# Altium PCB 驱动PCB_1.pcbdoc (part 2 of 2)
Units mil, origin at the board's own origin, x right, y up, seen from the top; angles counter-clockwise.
Board outline 1900 x 3705 mil, 2 copper layers (Top Layer, Bottom Layer); 43 components, 46 nets, 190 pads, 128 vias.
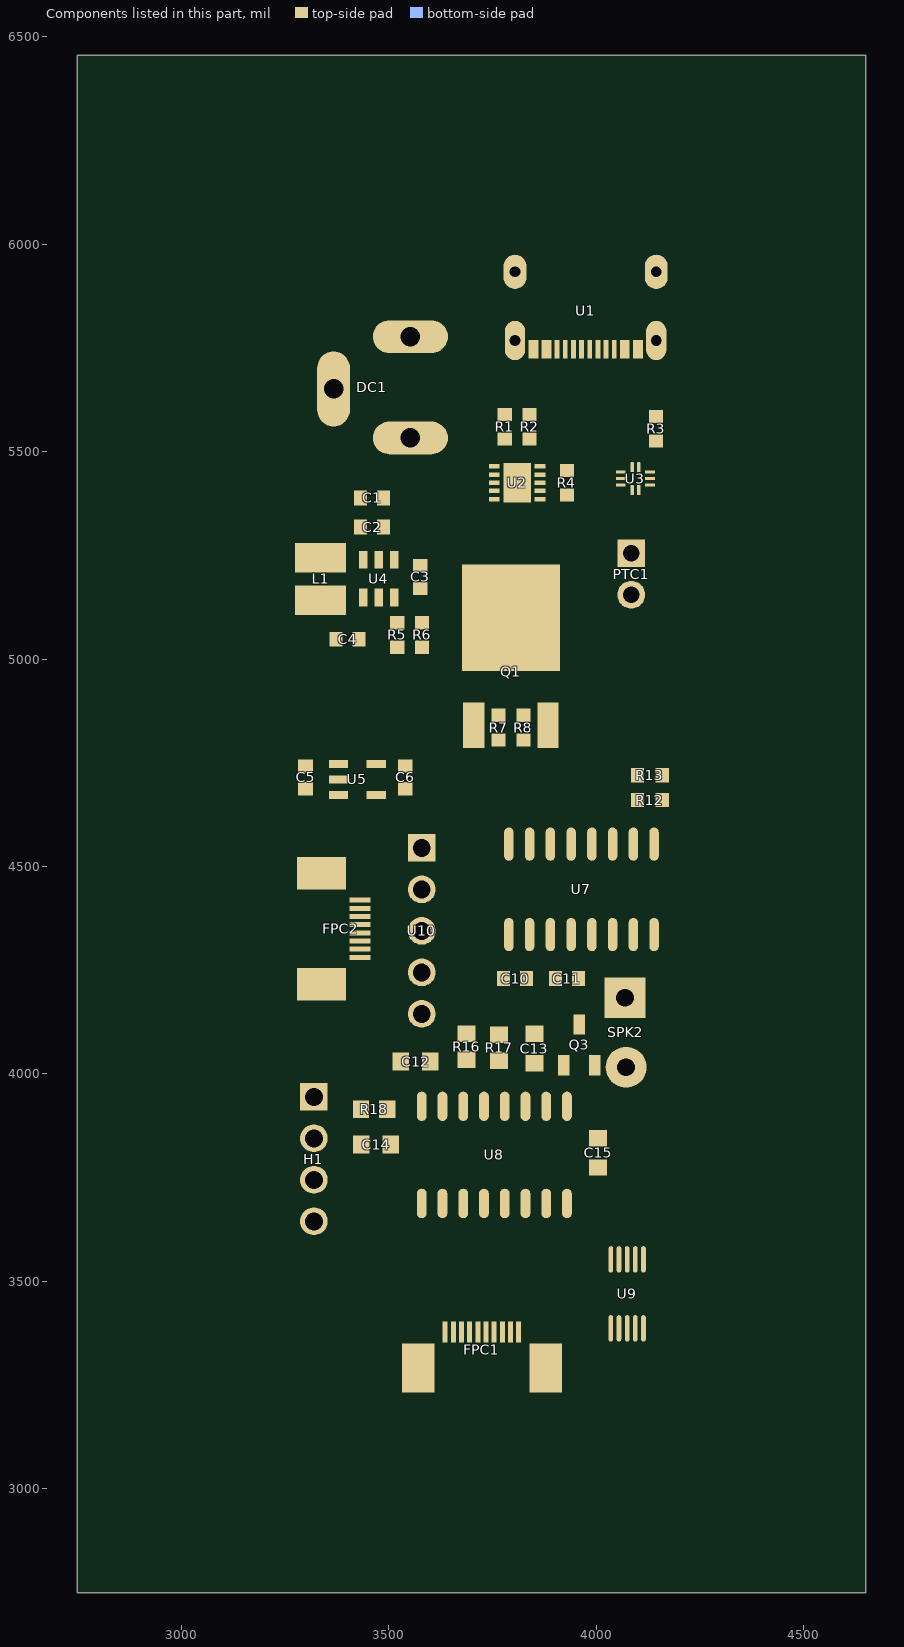
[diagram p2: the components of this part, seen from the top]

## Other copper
Top Layer:
  region net $2N1457: 3276.08,5208.01 3276.08,5283.01 3451.08,5283.01 3451.08,5208.01
  region net $2N1461: 3501.08,5167.61 3526.08,5168.01 3526.08,5113.01 3602.09,5113.01 3602.09,5069.79 3501.08,5069.79
  region net GND: 3486.08,5168.01 3461.84,5168.01 3461.84,5098.01 3406.08,5098.01 3406.08,4900.78 3486.08,4900.78
  region net VIN: 3461.17,5215.98 3461.17,5407.73 3460.78,5407.73 3460.78,5635 3565,5635 3665,5735 3665,5875 4060.98,5875 4060.98,5772.84 4013.78,5830 3945,5830 3890,5775 3886.42,5778.58 3886.42,5826.6 3786.6,5826.6 3765,5805 3765,5670 3667.98,5572.98 3667.98,5502.98 3572.73,5407.73 3544.82,5407.73 3544.82,5257.44 3526.04,5257.44 3525.67,5216.22 3502.75,5216.22 3502.99,5259.9 3488.36,5260 3488.36,5215.98
  region net 5V: 3275.85,4788.09 3276.08,4788.09 3276.08,5178.01 3391.08,5178.01 3391.08,4863.01 3499.71,4863.01 3499.71,5058.01 3553.49,5058.01 3553.49,4778.01 3436.91,4778.01 3436.91,4661.48 3355,4661.48 3355,4685 3409.89,4685 3409.89,4736.42 3330.25,4736.42 3330.25,4730.85 3275.85,4730.85
  region net GND: 3399.05,4720.38 3276.57,4720.31 3276.57,4629.64 3345.75,4629.64 3345,4700 3399.05,4700
  region net 3V3: 3445,4761.2 3445,4695 3500.97,4695 3500.97,4725.97 3560.45,4725.97 3560.45,4761.2
  region net 3V3: 3775,3335 3775,3285 3785,3275 3799.68,3275 3809.68,3285 3809.68,3335 3799.68,3345 3785,3345
  region net $2N1457: 3543.63,5203.34 3552.31,5226.16 ccw(c3536.35,5241.32) 3558.36,5241.32 3558.36,5209.82 ccw(c3559.34,5187.64)
  region net GND: 3437.91,5355.51 3427.91,5355.51 ccw(c3409.16,5355.51) 3420.41,5370.51 3445.41,5370.51 ccw(c3456.66,5355.51)
  region net GND: 3427.91,5350.94 3437.91,5350.94 ccw(c3456.66,5350.94) 3445.41,5335.94 3420.41,5335.94 ccw(c3409.16,5350.94)
  region net 3V3: 3553.98,4763.61 3562.18,4757.67 ccw(c3585.39,4742.6) 3557.72,4742.6 3538.07,4758.31 ccw(c3538.07,4784.82)
  region net $2N1719: 3835,4262.72 3845,4262.72 ccw(c3880.66,4262.72) 3848.31,4247.72 3827.5,4247.72 ccw(c3816.25,4262.72)
  region net $2N1719: 3863.31,4235 3863.31,4225 ccw(c3863.31,4206.25) 3848.31,4217.5 3848.31,4242.5 ccw(c3863.31,4253.75)
  region net $2N1719: 3871.69,4225 3871.69,4235 ccw(c3871.69,4253.75) 3886.69,4242.5 3886.69,4217.5 ccw(c3871.69,4206.25)
  region net $2N3517: 3500.43,3866.65 3510.43,3866.65 ccw(c3529.18,3866.65) 3517.93,3851.65 3492.93,3851.65 ccw(c3481.68,3866.65)
  region net A-: 3450.43,3787.07 3435.43,3787.07 ccw(c3409.69,3787.07) 3424.18,3808.35 3454.24,3808.35 ccw(c3511.64,3787.07)
  region net A-: 3392.38,3837.5 3392.38,3852.5 ccw(c3414.87,4151.1) 3414.88,3851.65 3414.88,3826.25 ccw(c3392.38,3809.38)
  region net E+: 3835.3,3999.27 3824.7,4009.87 ccw(c3782.88,4030.67) 3829.58,4030.67 3858.07,4006.12 ccw(c3858.07,3964.89)
  region net E+: 3824.28,4045.69 3833.32,4050.79 ccw(c3849.23,4072.01) 3849.23,4045.49 3829.58,4029.78 ccw(c3803.07,4029.78)
  region net E+: 3868.27,4053.45 3880.84,4044.81 ccw(c3912.66,4020.94) 3872.89,4020.94 3844.4,4045.49 ccw(c3844.4,4085.27)
  region net 3V3: 3975.39,3866 3989.54,3873.07 ccw(c4013.4,3904.89) 4013.4,3865.11 3983.35,3842.14 ccw(c3943.57,3842.14)
  region net 3V3: 3970.43,3837.93 3970.43,3852.93 ccw(c3970.43,3865.97) 3983.35,3864.18 3983.35,3826.68 ccw(c3970.43,3824.89)
  region net VIN: 3592.51,5422.48 3512.51,5422.48 3512.78,5429.14 3513.49,5435.75 3514.53,5442.25 3515.77,5448.59 3518.35,5460.61 3519.45,5466.17 3520.26,5471.37 3520.65,5476.15 3520.65,5478.37 3520.5,5480.47 3520.18,5482.43 3519.68,5484.26 3518.99,5485.94 3518.08,5487.48 3516.95,5488.86 3515.57,5490.07 3513.93,5491.12 3512.02,5491.99 3509.82,5492.68 3507.32,5493.18 3504.49,5493.49 3501.33,5493.59 3603.7,5493.59 3600.54,5493.49 3597.71,5493.18 3595.21,5492.68 3593.01,5491.99 3591.1,5491.12 3589.46,5490.07 3588.08,5488.86 3586.95,5487.48 3586.04,5485.94 3585.35,5484.26 3584.85,5482.43 3584.53,5480.47 3584.38,5478.37 3584.38,5476.15 3584.77,5471.37 3585.58,5466.17 3586.68,5460.61 3589.26,5448.59 3590.5,5442.25 3591.54,5435.75 3592.25,5429.14
  region net ADC_VIN: 3631.41,3418.59 3641.41,3418.59 ccw(c3763.07,3418.59) 3642.32,3403.77 3630.51,3403.77 ccw(c3509.76,3418.59)
  region net GND: 3661.11,3337.59 3651.11,3337.59 ccw(c3526.41,3337.59) 3650.2,3352.59 3662.01,3352.59 ccw(c3785.8,3337.59)
  region net 3V3: 3798.89,3337.59 3788.89,3337.59 ccw(c3664.2,3337.59) 3787.99,3352.59 3799.8,3352.59 ccw(c3923.59,3337.59)
  region net SW: 3834.49,3385 3834.49,3375 ccw(c3834.49,3356.25) 3819.49,3367.5 3819.49,3392.5 ccw(c3834.49,3403.75)
  region net VIN: 4129.07,5225.07 4114.93,5210.93 ccw(c4083.11,5168.5) 4083.11,5221.54 4118.46,5256.89 ccw(c4171.5,5256.89)
  region net $2N173: 4033.11,5195 4033.11,5115 ccw(c4033.11,4965) 3913.11,5055 3913.11,5227.56 ccw(c4033.11,5432.42)
  region net $2N169: 3746.11,4869.66 3746.11,4859.66 ccw(c3746.11,4840.91) 3731.11,4852.16 3731.11,4877.16 ccw(c3746.11,4888.41)
  region net E+: 3944.63,4111.7 3944.63,4126.7 ccw(c3905.64,4137.95) 3946.22,4137.95 3946.22,4100.45 ccw(c3905.64,4100.45)
  region net 3V3: 4004.9,3989.4 3989.9,3989.4 ccw(c3983.09,3989.4) 3983.62,3996.19 4011.18,3996.19 ccw(c4011.71,3989.4)
  region net $2N3503: 3896.34,3987.46 3900.93,4006.2 ccw(c3878.85,4028.28) 3908.82,4019.52 3908.82,3996.19 ccw(c3927.23,3956.57)
  region net $2N169: 3732.99,4859.66 3732.99,4869.66 ccw(c3732.99,4888.41) 3747.99,4877.16 3747.99,4852.16 ccw(c3732.99,4840.91)
  region net $2N169: 3797.01,4869.66 3797.01,4859.66 ccw(c3797.01,4840.91) 3782.01,4852.16 3782.01,4877.16 ccw(c3797.01,4888.41)
  region net PTC: 3787.31,4784.76 3773.77,4784.16 ccw(c3757.86,4762.95) 3757.86,4789.46 3782.01,4800.67 ccw(c3808.52,4800.67)
  region net $2N860: 3747.99,5525.34 3747.99,5535.34 ccw(c3747.99,5554.09) 3762.99,5542.84 3762.99,5517.84 ccw(c3747.99,5506.59)
  region net VIN: 3940,5375 3920,5375 ccw(c3912.99,5371.73) 3912.99,5379.46 3947.01,5379.46 ccw(c3947.01,5371.73)
  region net ADC_VIN: 4159.69,4637.62 4136.75,4628.82 ccw(c4119.2,4646.37) 4143.78,4642.99 4175.54,4642.99 ccw(c4175.54,4616.94)
  region net ADC_VIN: 4138.48,4674.79 4145.1,4682.31 ccw(c4161.01,4703.52) 4161.01,4677.01 4143.78,4658.88 ccw(c4117.27,4658.88)
  region net ADC_VIN: 4121.52,4705.89 4115.58,4697.69 ccw(c4099.67,4676.48) 4099.67,4702.99 4116.22,4721.8 ccw(c4142.73,4721.8)
  region net VIN: 4154.66,4752.01 4164.66,4752.01 ccw(c4183.41,4752.01) 4172.16,4737.01 4147.16,4737.01 ccw(c4135.91,4752.01)
  region net $2N169: 3792.99,4859.66 3792.99,4869.66 ccw(c3792.99,4888.41) 3807.99,4877.16 3807.99,4852.16 ccw(c3792.99,4840.91)
  region net $2N861: 3825.89,5509.16 3817.69,5515.1 ccw(c3796.48,5531.01) 3822.99,5531.01 3841.8,5514.46 ccw(c3841.8,5487.95)
  region net SW: 4150,5494.46 4140,5494.46 ccw(c4121.25,5494.46) 4132.5,5509.46 4157.5,5509.46 ccw(c4168.75,5494.46)
  region net E+: 3795.78,4088.33 3801.21,4068.76 ccw(c3779.13,4046.68) 3787.89,4076.65 3787.89,4101.65 ccw(c3817.86,4110.41)
  region net $2N3512: 3729.58,4026.75 3729.58,4036.75 ccw(c3729.58,4055.5) 3744.58,4044.25 3744.58,4019.25 ccw(c3729.58,4008)
  region net $2N3512: 3785,3997.06 3775,3997.06 ccw(c3756.25,3997.06) 3767.5,4012.06 3787.89,4012.06 ccw(c3825.38,3997.06)
  region net $2N3512: 3724.54,4036.75 3724.54,4026.75 ccw(c3724.54,4008) 3709.54,4019.25 3709.54,4044.25 ccw(c3724.54,4055.5)
  region net $2N3517: 3510.43,3878.35 3500.43,3878.35 ccw(c3481.68,3878.35) 3492.93,3893.35 3516.18,3893.35 ccw(c3532.86,3878.35)
  region net $2N3517: 3538.68,3922.5 3538.68,3907.5 ccw(c3538.68,3879.38) 3516.18,3896.25 3516.18,3933.75 ccw(c3538.68,3950.62)
  region net A+: 3405.87,3932.03 3414.51,3944.61 ccw(c3438.37,3976.43) 3438.37,3936.65 3413.82,3908.17 ccw(c3374.05,3908.17)
  region net SCK: 3685,3649.38 3675,3649.38 3674.71,3652.13 3673.94,3654.75 3672.84,3657.16 3671.59,3659.32 3669.25,3662.67 3668.48,3663.75 3668.19,3664.38 3691.81,3664.38 3691.52,3663.75 3690.75,3662.67 3688.41,3659.32 3687.16,3657.16 3686.06,3654.75 3685.29,3652.13
  region net DOUT: 3735,3649.38 3725,3649.38 3724.71,3652.13 3723.94,3654.75 3722.84,3657.16 3721.59,3659.32 3719.25,3662.67 3718.48,3663.75 3718.19,3664.38 3741.81,3664.38 3741.52,3663.75 3740.75,3662.67 3738.41,3659.32 3737.16,3657.16 3736.06,3654.75 3735.29,3652.13
  region net 3V3: 3922.5,3734.12 3937.5,3734.12 3937.69,3729.97 3938.17,3726 3938.86,3722.32 3939.66,3719.03 3941.14,3713.98 3941.81,3711.62 3918.19,3711.62 3918.86,3713.98 3920.34,3719.03 3921.14,3722.32 3921.83,3726 3922.31,3729.97
  region net 3V3: 3953.65,3674.96 3958.32,3649.07 3955.33,3652.48 3952.38,3656.4 3947.08,3663.93 3944.94,3666.58 3944.04,3667.42 3943.27,3667.86 3942.65,3667.83 3942.19,3667.28 3941.91,3666.15 3941.81,3664.38 3941.81,3694.94 3942.08,3691.92 3942.83,3689.12 3944,3686.5 3945.51,3684.03 3947.3,3681.67 3949.3,3679.4
  region net $2N3517: 3545.69,3907.5 3545.69,3922.5 3549.89,3922.52 3553.95,3922.68 3557.75,3923.09 3561.16,3923.91 3562.67,3924.5 3564.04,3925.25 3565.24,3926.16 3566.26,3927.25 3567.08,3928.53 3567.68,3930.04 3568.06,3931.77 3568.19,3933.75 3568.19,3898.38 3568.06,3900.33 3567.68,3902 3567.08,3903.4 3566.26,3904.55 3565.24,3905.48 3564.04,3906.21 3562.67,3906.76 3561.16,3907.16 3557.75,3907.58 3553.95,3907.66
  region net A-: 3637.5,3875.88 3622.5,3875.88 3622.31,3880.03 3621.83,3884 3621.14,3887.68 3620.34,3890.97 3618.86,3896.02 3618.19,3898.38 3641.81,3898.38 3641.14,3896.02 3639.66,3890.97 3638.86,3887.68 3638.17,3884 3637.69,3880.03
  region net $2N3514: 3675,3960.62 3685,3960.62 3685.29,3957.87 3686.06,3955.25 3687.16,3952.84 3688.41,3950.68 3690.75,3947.33 3691.52,3946.25 3691.81,3945.62 3668.19,3945.62 3668.48,3946.25 3669.25,3947.33 3671.59,3950.68 3672.84,3952.84 3673.94,3955.25 3674.71,3957.87
  region net $2N3512: 3775,3960.62 3785,3960.62 3785.29,3957.87 3786.06,3955.25 3787.16,3952.84 3788.41,3950.68 3790.75,3947.33 3791.52,3946.25 3791.81,3945.62 3768.19,3945.62 3768.48,3946.25 3769.25,3947.33 3771.59,3950.68 3772.84,3952.84 3773.94,3955.25 3774.71,3957.87
  region net E+: 3822.5,3968.12 3837.5,3968.12 3837.69,3963.97 3838.17,3960 3838.86,3956.32 3839.66,3953.03 3841.14,3947.98 3841.81,3945.62 3818.19,3945.62 3818.86,3947.98 3820.34,3953.03 3821.14,3956.32 3821.83,3960 3822.31,3963.97
  region net E+: 3840,3868.38 3820,3868.38 3819.72,3879.25 3819.09,3888.63 3818.19,3898.38 3841.81,3898.38 3840.91,3888.63 3840.28,3879.25
  region net $2N3503: 3875,3960.62 3885,3960.62 3885.29,3957.87 3886.06,3955.25 3887.16,3952.84 3888.41,3950.68 3890.75,3947.33 3891.52,3946.25 3891.81,3945.62 3868.19,3945.62 3868.48,3946.25 3869.25,3947.33 3871.59,3950.68 3872.84,3952.84 3873.94,3955.25 3874.71,3957.87
  region net 3V3: 3953.65,3908.96 3958.32,3883.07 3955.33,3886.48 3952.38,3890.4 3947.08,3897.93 3944.94,3900.58 3944.04,3901.42 3943.27,3901.86 3942.65,3901.83 3942.19,3901.28 3941.91,3900.15 3941.81,3898.38 3941.81,3928.94 3942.08,3925.92 3942.83,3923.12 3944,3920.5 3945.51,3918.03 3947.3,3915.67 3949.3,3913.4
  region net 3V3: 3958.32,3960.93 3953.65,3935.04 3949.3,3930.6 3947.3,3928.33 3945.51,3925.97 3944,3923.5 3942.83,3920.88 3942.08,3918.08 3941.81,3915.06 3941.81,3945.62 3941.91,3943.85 3942.19,3942.72 3942.65,3942.17 3943.27,3942.14 3944.04,3942.58 3944.94,3943.42 3947.08,3946.07 3952.38,3953.6 3955.33,3957.52
  region net $2N1457: 3449.36,5209.02 3439.36,5209.02 ccw(c3430.5,5209.02) 3431.86,5217.77 3449.22,5217.77 ccw(c3721.11,5217.77)
  region net $2N1458: 3433.74,5172.82 3443.74,5172.82 ccw(c3449.22,5175.66) 3449.22,5169.49 3428.27,5169.49 ccw(c3428.27,5175.66)
  region net CC1: 4029.21,5719.56 4019.21,5719.56 ccw(c4006.64,5719.56) 4018.3,5724.24 4030.12,5724.24 ccw(c4041.78,5719.56)
  region net CC2: 3911.1,5709.24 3901.1,5709.24 ccw(c3776.41,5709.24) 3900.19,5724.24 3912.01,5724.24 ccw(c4035.79,5709.24)
  region net VIN: 4077.5,5710 4062.5,5710 ccw(c4051.47,5724.24) 4069.48,5724.24 4081.3,5724.24 ccw(c4106.12,5710)
  region net CC1: 3890,5449.69 3890,5439.69 ccw(c3890,5310.3) 3878.5,5439.18 3878.5,5450.2 ccw(c3890,5579.08)
  region net CC2: 3860.41,5480.41 3870.41,5480.41 ccw(c3881.55,5480.41) 3877.91,5469.88 3852.91,5469.88 ccw(c3849.27,5480.41)
  region net USBDM: 3985,4597.84 3995,4597.84 3995.27,4595.08 3995.98,4592.47 3996.99,4590.06 3998.15,4587.9 4000.31,4584.55 4001.03,4583.46 4001.3,4582.84 3978.7,4582.84 3978.97,4583.46 3979.69,4584.55 3981.85,4587.9 3983.01,4590.06 3984.02,4592.47 3984.73,4595.08
  region net USBDP: 3935,4597.84 3945,4597.84 3945.27,4595.08 3945.98,4592.47 3946.99,4590.06 3948.15,4587.9 3950.31,4584.55 3951.03,4583.46 3951.3,4582.84 3928.7,4582.84 3928.97,4583.46 3929.69,4584.55 3931.85,4587.9 3933.01,4590.06 3934.02,4592.47 3934.73,4595.08
  region net CH7800_RX: 4159.19,4323.86 4164.62,4304.29 4160.23,4308.92 4158,4311.23 4155.91,4313.19 4154.07,4314.53 4153.29,4314.88 4152.61,4314.98 4152.06,4314.8 4151.65,4314.29 4151.39,4313.43 4151.3,4312.18 4151.3,4337.18 4151.48,4335.17 4151.98,4333.3 4152.76,4331.55 4153.77,4329.91 4154.96,4328.34 4156.29,4326.82
  region net CH7800_TX: 4104.14,4297.93 4094.91,4293.02 4092.91,4294.67 4091.06,4295.62 4089.32,4296.12 4087.66,4296.41 4086.03,4296.73 4084.4,4297.33 4082.74,4298.44 4081,4300.33 4099,4314 4099.83,4312.77 4100.44,4311.62 4101.11,4309.49 4101.29,4307.53 4101.25,4305.68 4101.24,4303.86 4101.54,4302.01 4101.89,4301.05 4102.42,4300.06 4103.16,4299.02
  region net SPK1: 4047.5,4284.66 4032.5,4284.66 4032.34,4288.82 4031.91,4292.78 4031.3,4296.46 4030.6,4299.75 4029.29,4304.81 4028.7,4307.16 4051.3,4307.16 4050.71,4304.81 4049.4,4299.75 4048.7,4296.46 4048.09,4292.78 4047.66,4288.82
  region net SPK2: 3997.5,4284.66 3982.5,4284.66 3982.34,4288.82 3981.91,4292.78 3981.3,4296.46 3980.6,4299.75 3979.29,4304.81 3978.7,4307.16 4001.3,4307.16 4000.71,4304.81 3999.4,4299.75 3998.7,4296.46 3998.09,4292.78 3997.66,4288.82
  region net 5V: 3868.24,4386.16 3890.14,4385.46 3892.22,4383.3 3894.24,4380.99 3896.12,4378.55 3897.81,4376 3899.24,4373.33 3900.34,4370.57 3901.05,4367.72 3901.3,4364.8 3878.7,4364.8 3878.47,4367.63 3877.8,4370.52 3876.77,4373.43 3875.43,4376.29 3873.85,4379.05 3872.08,4381.65 3870.19,4384.04
  region net $2N1719: 3845,4292.16 3835,4292.16 3834.73,4294.92 3834.02,4297.53 3833.01,4299.94 3831.85,4302.1 3829.69,4305.45 3828.97,4306.54 3828.7,4307.16 3851.3,4307.16 3851.03,4306.54 3850.31,4305.45 3848.15,4302.1 3846.99,4299.94 3845.98,4297.53 3845.27,4294.92
  region net SW: 4135.18,5462.57 4148.54,5461.78 ccw(c7232.44,2377.87) 4141.45,5454.68 4121.86,5454.68 ccw(c4113.1,5484.65)
  region net GND: 4037.95,5465.3 4054.82,5462.57 ccw(c4076.9,5484.65) 4068.14,5454.68 4048.55,5454.68 ccw(c-2852.18,-1424.92)
  region net 3V3: 4022.23,3395.7 4021.44,3410.63 4024.18,3408.09 4025.63,3406.94 4027.01,3406.04 4028.24,3405.51 4029.22,3405.47 4029.6,3405.68 4029.88,3406.06 4030.06,3406.62 4030.12,3407.38 4030.12,3382.38 4029.94,3384.39 4029.44,3386.26 4028.66,3388.01 4027.65,3389.66 4026.46,3391.23 4025.12,3392.74
  region net SW: 4099.69,3349.69 4089.69,3349.69 4089.43,3356.78 4089.18,3360.55 4100.2,3360.55 4099.95,3356.78
  region net CH7800_RX: 4131.93,3391.93 4131.93,3381.93 4129.68,3381.85 4127.51,3381.61 4125.47,3381.15 4123.65,3380.44 4122.11,3379.45 4120.92,3378.14 4120.15,3376.48 4119.88,3374.43 4119.88,3399.43 4120.15,3397.38 4120.92,3395.72 4122.11,3394.41 4123.65,3393.42 4125.47,3392.71 4127.51,3392.25 4129.68,3392.01
  region net DOUT: 4015.12,3548.07 4015.12,3558.07 4020.63,3558.19 4023.16,3558.47 4025.43,3559.01 4027.35,3559.9 4028.15,3560.51 4028.83,3561.23 4029.38,3562.09 4029.78,3563.09 4030.03,3564.25 4030.12,3565.57 4030.12,3540.57 4030.03,3541.89 4029.78,3543.05 4029.38,3544.05 4028.83,3544.91 4028.15,3545.63 4027.35,3546.24 4025.43,3547.13 4023.16,3547.67 4020.63,3547.95
  region net ESP_RX: 4060.32,3511.69 4050.32,3511.69 4050.06,3521.63 4049.81,3526.69 4060.83,3526.69 4060.58,3521.63
  region net SPK2: 4030.87,4092.24 4075.02,4069.31 4077.31,4067.16 4079.47,4065.43 4081.5,4064.06 4083.43,4062.98 4085.28,4062.15 4087.07,4061.49 4090.56,4060.49 4094.07,4059.51 4095.88,4058.87 4097.76,4058.07 4099.72,4057.03 4101.8,4055.7 4104,4054.02 4106.36,4051.93 4033.25,4045.9 4034.9,4048.36 4036.32,4051.03 4037.49,4053.88 4038.43,4056.86 4039.12,4059.96 4039.58,4063.14 4039.79,4066.37 4039.77,4069.61 4039.5,4072.83 4038.99,4076.01 4038.24,4079.1 4037.25,4082.08 4036.02,4084.92 4034.55,4087.58 4032.83,4090.03
  region net SPK2: 4030.9,4092.21 4075.78,4068.55 4078.08,4066.4 4080.24,4064.68 4082.29,4063.32 4084.24,4062.26 4086.1,4061.44 4087.91,4060.81 4091.44,4059.84 4094.96,4058.88 4096.77,4058.25 4098.65,4057.43 4100.6,4056.38 4102.65,4055.03 4104.82,4053.32 4107.13,4051.18 4033.04,4045.63 4034.7,4048.13 4036.13,4050.82 4037.33,4053.69 4038.29,4056.7 4039.01,4059.81 4039.5,4063 4039.74,4066.24 4039.74,4069.48 4039.5,4072.71 4039.02,4075.89 4038.29,4078.99 4037.31,4081.98 4036.08,4084.83 4034.61,4087.51 4032.88,4089.98
  region net SPK1: 4034.7,4253.47 4111.26,4198.12 ccw(c4131.15,4198.12) 4115.23,4186.19 4119.21,4174.26 4039.27,4232.99 ccw(c4020.85,4239.63)
  region net A+: 3375.96,3952.5 3375.96,3937.5 ccw(c3375.96,3909.38) 3353.46,3926.25 3353.46,3963.75 ccw(c3375.96,3980.62)
  region net A-: 3365.73,3852.5 3365.73,3837.5 3363.42,3837.4 3361.37,3837.11 3359.55,3836.64 3357.93,3836 3356.47,3835.21 3355.14,3834.28 3352.77,3832.05 3350.56,3829.41 3348.24,3826.46 3345.58,3823.31 3342.31,3820.06 3342.31,3869.94 3345.58,3866.69 3348.24,3863.54 3350.56,3860.59 3352.77,3857.95 3355.14,3855.72 3356.47,3854.79 3357.93,3854 3359.55,3853.36 3361.37,3852.89 3363.42,3852.6
  region net E+: 3357.26,3765 3372.17,3745 3370.32,3744.9 3368.51,3744.62 3366.74,3744.15 3365.02,3743.53 3361.72,3741.84 3358.63,3739.64 3355.77,3737.05 3353.16,3734.16 3350.81,3731.06 3348.74,3727.86 3333.84,3775.47 3337.63,3773.52 3340.58,3771.63 3345.12,3768.27 3347.33,3766.93 3349.88,3765.9 3353.09,3765.24
  region net CC1: 4015,5590 4015,5600 4016.06,5600.09 4017.03,5600.34 4018.78,5601.23 4020.39,5602.5 4021.99,5603.95 4021.99,5586.05 4020.39,5587.5 4018.78,5588.77 4017.03,5589.66 4016.06,5589.91
  region net VIN: 3867.11,5698.8 3882.11,5704.87 3882.02,5703.41 3881.81,5702.05 3881.42,5699.62 3881.44,5698.59 3881.75,5697.72 3882.42,5697 3883.58,5696.46 3868.39,5688.05 3868.62,5689.44 3868.61,5690.78 3868.12,5693.38 3867.45,5696 3867.21,5697.37
  region net VIN: 3867.11,5727.76 3882.11,5727.76 3882.02,5725.38 3881.99,5723.24 3882.11,5722.24 3882.38,5721.26 3882.85,5720.31 3883.56,5719.36 3865.66,5719.36 3866.37,5720.31 3866.84,5721.26 3867.11,5722.24 3867.23,5723.24 3867.2,5725.38
  region net VIN: 3882.11,5694.94 3867.11,5694.94 3867.2,5697.33 3867.23,5699.47 3867.11,5700.47 3866.84,5701.45 3866.37,5702.4 3865.66,5703.35 3883.56,5703.35 3882.85,5702.4 3882.38,5701.45 3882.11,5700.47 3881.99,5699.47 3882.02,5697.33
  region net VIN: 4062.5,5726.41 4077.5,5726.41 4077.41,5724.02 4077.38,5721.88 4077.5,5720.88 4077.77,5719.91 4078.24,5718.95 4078.95,5718.01 4061.05,5718.01 4061.76,5718.95 4062.23,5719.91 4062.5,5720.88 4062.62,5721.88 4062.59,5724.02
  region net 5V: 3886.91,4388.7 3876.3,4378.09 3874.68,4379.85 3873.19,4381.38 3872.39,4382 3871.51,4382.5 3870.51,4382.84 3869.33,4383.01 3881.99,4395.67 3882.16,4394.49 3882.5,4393.49 3883,4392.61 3883.62,4391.81 3885.15,4390.32
  region net USBDP: 3975,4643.59 3965,4643.59 3964.91,4644.71 3964.66,4645.84 3963.77,4648.07 3962.5,4650.17 3961.05,4651.99 3978.95,4651.99 3977.5,4650.17 3976.23,4648.07 3975.34,4645.84 3975.09,4644.71
  region net USBDM: 4015,4643.56 4005,4643.62 4004.91,4644.74 4004.66,4645.88 4003.77,4648.11 4002.51,4650.2 4001.07,4652.03 4018.97,4651.96 4017.51,4650.14 4016.24,4648.04 4015.34,4645.81 4015.09,4644.68
  region net USBDM: 4078.07,5380.14 4085.14,5373.07 4084.41,5372.21 4083.79,5371.24 4082.84,5369.02 4082.26,5366.65 4081.99,5364.33 4069.33,5376.99 4071.65,5377.26 4074.02,5377.84 4076.24,5378.79 4077.21,5379.41
  region net ESP_RX: 4050.32,3524.55 4060.32,3518.73 4060.64,3513.43 4061.04,3510.65 4061.57,3508.21 4045.52,3516.14 4046.59,3516.72 4047.54,3517.51 4048.36,3518.48 4049.05,3519.58 4049.59,3520.78 4049.99,3522.04 4050.24,3523.31
  region net DN1: 3998.07,5430.14 4005.14,5423.07 4004.41,5422.21 4003.79,5421.24 4002.84,5419.02 4002.26,5416.65 4001.99,5414.33 3989.33,5426.99 3991.65,5427.26 3994.02,5427.84 3996.24,5428.79 3997.21,5429.41
  region net DP1: 4008.07,5390.14 4015.14,5383.07 4014.41,5382.21 4013.79,5381.24 4012.84,5379.02 4012.26,5376.65 4011.99,5374.33 3999.33,5386.99 4001.65,5387.26 4004.02,5387.84 4006.24,5388.79 4007.21,5389.41
  region net PTC: 3779.86,4778.07 3786.93,4785.14 3787.79,4784.41 3788.76,4783.79 3790.98,4782.84 3793.35,4782.26 3795.67,4781.99 3783.01,4769.33 3782.74,4771.65 3782.16,4774.02 3781.21,4776.24 3780.59,4777.21
  region net ADC_VIN: 3585,3478.59 3575,3478.59 3574.91,3479.71 3574.66,3480.84 3573.77,3483.07 3572.5,3485.17 3571.05,3486.99 3588.95,3486.99 3587.5,3485.17 3586.23,3483.07 3585.34,3480.84 3585.09,3479.71
  region net ADC_VIN: 3906.41,4425 3906.41,4415 3905.29,4414.91 3904.16,4414.66 3901.93,4413.77 3899.83,4412.5 3898.01,4411.05 3898.01,4428.95 3899.83,4427.5 3901.93,4426.23 3904.16,4425.34 3905.29,4425.09
  region net SW: 4163.07,5355.14 4170.14,5348.07 4169.41,5347.21 4168.79,5346.24 4167.84,5344.02 4167.26,5341.65 4166.99,5339.33 4154.33,5351.99 4156.65,5352.26 4159.02,5352.84 4161.24,5353.79 4162.21,5354.41
  region net SW: 4080,3618.59 4070,3618.59 4069.91,3619.71 4069.66,3620.84 4068.77,3623.07 4067.5,3625.17 4066.05,3626.99 4083.95,3626.99 4082.5,3625.17 4081.23,3623.07 4080.34,3620.84 4080.09,3619.71
  region net 3V3: 3645,5113.59 3635,5113.59 3634.91,5114.71 3634.66,5115.84 3633.77,5118.07 3632.5,5120.17 3631.05,5121.99 3648.95,5121.99 3647.5,5120.17 3646.23,5118.07 3645.34,5115.84 3645.09,5114.71
  region net 3V3: 3788.89,3335.76 3798.89,3335.76 3798.98,3334.64 3799.23,3333.51 3800.13,3331.28 3801.39,3329.19 3802.85,3327.36 3784.94,3327.36 3786.4,3329.19 3787.66,3331.28 3788.56,3333.51 3788.81,3334.64
  region net GND: 4019.32,5498.07 4008.76,5494.48 4007.08,5495.86 4005.16,5496.98 4003.12,5497.89 4001.05,5498.66 4016.71,5507.34 4016.56,5506.24 4016.58,5505.02 4017.05,5502.42 4018,5499.96 4018.62,5498.92
  region net GND: 4128.25,5332.89 4135.32,5325.82 4134.59,5324.96 4133.96,5323.99 4133.02,5321.78 4132.43,5319.4 4132.17,5317.08 4119.51,5329.74 4121.83,5330.01 4124.2,5330.59 4126.41,5331.54 4127.39,5332.16
  region net GND: 4140,5352.52 4130,5352.52 4129.91,5353.47 4129.66,5354.16 4129.27,5354.65 4128.77,5355.04 4127.5,5355.78 4126.79,5356.29 4126.05,5356.99 4143.95,5356.99 4143.21,5356.29 4142.5,5355.78 4141.23,5355.04 4140.73,5354.65 4140.34,5354.16 4140.09,5353.47
  region net GND: 4121.94,5380.48 4132.59,5383.97 4137.26,5379.02 4139.38,5376.95 4142.32,5374.52 4125.01,5371.66 4125.59,5372.84 4125.8,5374 4125.67,5375.13 4125.27,5376.25 4124.65,5377.34 4123.85,5378.41
  region net 3V3: 3993.56,3613.83 4006.41,3622.2 4008,3620.35 4009.22,3618.78 4009.86,3618.11 4010.63,3617.54 4011.57,3617.06 4012.78,3616.68 3998.08,3606.46 3998.11,3607.65 3997.89,3608.7 3997.47,3609.64 3996.88,3610.51 3995.35,3612.14
  region net 3V3: 4001.3,3401.91 4011.91,3391.3 4010.15,3389.68 4008.62,3388.19 4008,3387.39 4007.5,3386.51 4007.16,3385.51 4006.99,3384.33 3994.33,3396.99 3995.51,3397.16 3996.51,3397.5 3997.39,3398 3998.19,3398.62 3999.68,3400.15
  region net VIN: 4156.12,4903.8 ccw(c4142.49,4882.08) 4124.36,4900.21 4138.5,4928.5 4166.78,4942.64 ccw(c4184.92,4924.51) 4163.2,4910.87
  region net VIN: 3937.07,5367.93 ccw(c4014.14,5441.66) 4014.14,5335 3890,5295 3765.86,5335 ccw(c3765.86,5620.6) 3922.93,5382.07
  region net 3V3: 4035.84,3396.23 4028.77,3389.16 ccw(c3710.48,3070.88) 4017.98,3399.59 4025.41,3407.02 ccw(c4354.12,3714.52)
Bottom Layer:
  region net 3V3: 3445,4761.2 3445,4695 3501.8,4695 3501.8,4725.97 3530.71,4725.97 3530.71,4761.2
  region net GND: 3770,5475 3770,5375 3844.01,5375 3845.02,5376.01 3845.02,5475
  region net GND: 3664.12,5787.04 3664.12,5767.04 3662.25,5766.95 3660.3,5766.7 3656.2,5765.75 3651.99,5764.27 3647.79,5762.35 3643.76,5760.08 3640.04,5757.55 3636.78,5754.84 3634.12,5752.04 3634.12,5802.04 3636.78,5799.24 3640.04,5796.53 3643.76,5794 3647.79,5791.73 3651.99,5789.81 3656.2,5788.33 3660.3,5787.38 3662.25,5787.13
  region net GND: 3753.47,5767.04 3753.47,5787.04 3755.96,5786.93 3758.44,5786.64 3763.25,5785.69 3767.75,5784.59 3771.79,5783.72 3773.58,5783.49 3775.2,5783.47 3776.62,5783.71 3777.82,5784.24 3778.8,5785.13 3779.52,5786.42 3779.96,5788.15 3780.11,5790.39 3780.11,5752.04 3779.96,5754.4 3779.52,5756.51 3778.8,5758.37 3777.82,5760 3776.62,5761.42 3775.2,5762.64 3773.58,5763.67 3771.79,5764.54 3769.84,5765.24 3767.75,5765.81 3763.25,5766.57 3758.44,5766.94
  region net DP: 3971.46,5791.46 3978.54,5798.54 3979.32,5797.87 3980.12,5797.43 3980.93,5797.17 3981.78,5797.04 3985.67,5796.99 3973.01,5784.33 3972.96,5788.22 3972.83,5789.07 3972.57,5789.88 3972.13,5790.68
  region net DP: 3955.43,5800 3955.43,5790 3954.31,5789.91 3953.17,5789.66 3950.94,5788.77 3948.85,5787.5 3947.02,5786.05 3947.02,5803.95 3948.85,5802.5 3950.94,5801.23 3953.17,5800.34 3954.31,5800.09
  region net CC1: 4080.18,5638.11 4071.55,5643.62 4072.27,5644.48 4072.89,5645.49 4073.82,5647.82 4074.32,5650.31 4074.4,5652.66 4088.52,5641.65 4086.28,5641.17 4084.04,5640.47 4081.96,5639.47
  region net CC1: 4038.07,5610.14 4045.14,5603.07 4044.41,5602.21 4043.79,5601.24 4042.84,5599.02 4042.26,5596.65 4041.99,5594.33 4029.33,5606.99 4031.65,5607.26 4034.02,5607.84 4036.24,5608.79 4037.21,5609.41
  region net 5V: 3853.59,4387.5 3853.59,4402.5 3855.98,4402.41 3858.12,4402.38 3859.12,4402.5 3860.09,4402.77 3861.05,4403.24 3861.99,4403.95 3861.99,4386.05 3861.05,4386.76 3860.09,4387.23 3859.12,4387.5 3858.12,4387.62 3855.98,4387.59
  region net USBDP: 3984.25,4647.82 3973.45,4644.47 3971.79,4645.85 3969.89,4646.99 3967.86,4647.94 3965.83,4648.74 3981.65,4657.11 3981.49,4656.02 3981.5,4654.8 3981.97,4652.19 3982.92,4649.72 3983.55,4648.67
  region net USBDM: 4005.05,4676.41 4015.05,4676.41 4015.13,4675.29 4015.39,4674.16 4016.28,4671.93 4017.55,4669.83 4019,4668.01 4001.1,4668.01 4002.55,4669.83 4003.81,4671.93 4004.71,4674.16 4004.96,4675.29
  region net USBDM: 4061.93,5349.86 4054.86,5356.93 4055.59,5357.79 4056.21,5358.76 4057.16,5360.98 4057.74,5363.35 4058.01,5365.67 4070.67,5353.01 4068.35,5352.74 4065.98,5352.16 4063.76,5351.21 4062.79,5350.59
  region net USBDP: 4094.84,5340.23 4089.61,5349.14 4090.98,5350.91 4091.99,5352.97 4092.71,5355.18 4093.23,5357.4 4103.92,5343.04 4101.58,5343 4099.07,5342.5 4096.72,5341.57 4095.7,5340.95
  region net ESP_TX: 4052.82,3460.75 4049.47,3471.55 4050.85,3473.21 4051.99,3475.11 4052.94,3477.14 4053.74,3479.17 4062.11,3463.35 4061.02,3463.51 4059.8,3463.5 4057.19,3463.03 4054.72,3462.08 4053.67,3461.45
  region net ESP_RX: 4041.93,3489.86 4034.86,3496.93 4035.59,3497.79 4036.21,3498.76 4037.16,3500.98 4037.74,3503.35 4038.01,3505.67 4050.67,3493.01 4048.35,3492.74 4045.98,3492.16 4043.76,3491.21 4042.79,3490.59
  region net ESP_RX: 3768.07,3470.14 3775.14,3463.07 3774.41,3462.21 3773.79,3461.24 3772.84,3459.02 3772.26,3456.65 3771.99,3454.33 3759.33,3466.99 3761.65,3467.26 3764.02,3467.84 3766.24,3468.79 3767.21,3469.41
  region net DN1: 3700,3506.41 3710,3506.41 3710.09,3505.29 3710.34,3504.16 3711.23,3501.93 3712.5,3499.83 3713.95,3498.01 3696.05,3498.01 3697.5,3499.83 3698.77,3501.93 3699.66,3504.16 3699.91,3505.29
  region net DP1: 3743.45,3500.53 3754.25,3497.18 3753.55,3496.33 3752.92,3495.28 3751.97,3492.81 3751.5,3490.2 3751.49,3488.98 3751.65,3487.89 3735.83,3496.26 3737.86,3497.06 3739.89,3498.01 3741.79,3499.15
  region net DN1: 3981.93,5399.86 3974.86,5406.93 3975.59,5407.79 3976.21,5408.76 3977.16,5410.98 3977.74,5413.35 3978.01,5415.67 3990.67,5403.01 3988.35,5402.74 3985.98,5402.16 3983.76,5401.21 3982.79,5400.59
  region net DP1: 3987.82,5360.75 3984.47,5371.55 3985.85,5373.21 3986.99,5375.11 3987.94,5377.14 3988.74,5379.17 3997.11,5363.35 3996.02,5363.51 3994.8,5363.5 3992.19,5363.03 3989.72,5362.08 3988.67,5361.45
  region net PTC: 3650,3496.41 3660,3496.41 3660.09,3495.29 3660.34,3494.16 3661.23,3491.93 3662.5,3489.83 3663.95,3488.01 3646.05,3488.01 3647.5,3489.83 3648.77,3491.93 3649.66,3494.16 3649.91,3495.29
  region net PTC: 3810.14,4761.93 3803.07,4754.86 3802.21,4755.59 3801.24,4756.21 3799.02,4757.16 3796.65,4757.74 3794.33,4758.01 3806.99,4770.67 3807.26,4768.35 3807.84,4765.98 3808.79,4763.76 3809.41,4762.79
  region net ADC_VIN: 3575,3511.41 3585,3511.41 3585.09,3510.29 3585.34,3509.16 3586.23,3506.93 3587.5,3504.83 3588.95,3503.01 3571.05,3503.01 3572.5,3504.83 3573.77,3506.93 3574.66,3509.16 3574.91,3510.29
  region net ADC_VIN: 3895,4407.52 3885,4407.52 3884.91,4408.47 3884.66,4409.15 3884.27,4409.65 3883.77,4410.04 3882.5,4410.78 3881.79,4411.29 3881.05,4411.99 3898.95,4411.99 3898.21,4411.29 3897.5,4410.78 3896.23,4410.04 3895.73,4409.65 3895.34,4409.15 3895.09,4408.47
  region net SW: 4170.14,5331.93 4163.07,5324.86 4162.21,5325.59 4161.24,5326.21 4159.02,5327.16 4156.65,5327.74 4154.33,5328.01 4166.99,5340.67 4167.26,5338.35 4167.84,5335.98 4168.79,5333.76 4169.41,5332.79
  region net SW: 4070,3651.41 4080,3651.41 4080.09,3650.29 4080.34,3649.16 4081.23,3646.93 4082.5,3644.83 4083.95,3643.01 4066.05,3643.01 4067.5,3644.83 4068.77,3646.93 4069.66,3649.16 4069.91,3650.29
  region net 3V3: 3648.07,5145.14 3655.14,5138.07 3654.41,5137.21 3653.79,5136.24 3652.84,5134.02 3652.26,5131.65 3651.99,5129.33 3639.33,5141.99 3641.65,5142.26 3644.02,5142.84 3646.24,5143.79 3647.21,5144.41
  region net 3V3: 4125.52,5397.41 4130.11,5406.96 4132.29,5404.86 4133.37,5403.97 4134.46,5403.28 4135.56,5402.86 4136.66,5402.77 4137.78,5403.08 4138.91,5403.87 4139.07,5385.99 4135.64,5388.86 4132.2,5391.6 4128.8,5394.39
  region net 3V3: 3778.89,3297.3 3808.89,3304.51 3808.69,3303.79 3808.13,3303.1 3807.27,3302.42 3806.15,3301.77 3803.42,3300.54 3800.39,3299.41 3797.53,3298.39 3795.3,3297.5 3794.56,3297.1 3794.16,3296.73 3794.14,3296.4 3794.57,3296.11 3778.64,3288.89 3779.21,3291.2 3779.23,3293.02 3779.03,3294.88
  region net GND: 3789.41,4500 3789.41,4480 3786.76,4479.91 3784.26,4479.69 3779.88,4479 3776.66,4478.31 3775,4477.99 3775,4502.01 3776.66,4501.69 3779.88,4501 3784.26,4500.31 3786.76,4500.09
  region net GND: 3758.95,4501.91 3776.13,4513.01 3776.92,4512.11 3777.49,4511.22 3778.13,4509.48 3778.3,4507.79 3778.26,4506.16 3778.27,4504.59 3778.58,4503.09 3778.93,4502.37 3779.46,4501.66 3780.19,4500.97 3781.16,4500.31 3764.22,4495.29 3764.62,4496.5 3764.55,4497.45 3764.09,4498.22 3763.32,4498.89 3761.23,4500.18 3760.07,4500.95
  region net GND: 3786.31,4480 3786.61,4500 3787.73,4499.79 3788.86,4499.25 3791.09,4497.74 3792.16,4497.05 3793.18,4496.6 3794.14,4496.52 3795.01,4496.95 3794.71,4479.28 3793.71,4480.07 3792.77,4480.51 3791.84,4480.67 3790.91,4480.63 3788.84,4480.26
  region net 3V3: 4026.91,3598.7 4016.3,3588.09 4014.68,3589.85 4013.19,3591.38 4012.39,3592 4011.51,3592.5 4010.51,3592.84 4009.33,3593.01 4021.99,3605.67 4022.16,3604.49 4022.5,3603.49 4023,3602.61 4023.62,3601.81 4025.15,3600.32
  region net 3V3: 4011.91,3378.7 4001.3,3368.09 3999.68,3369.85 3998.19,3371.38 3997.39,3372 3996.51,3372.5 3995.51,3372.84 3994.33,3373.01 4006.99,3385.67 4007.16,3384.49 4007.5,3383.49 4008,3382.61 4008.62,3381.81 4010.15,3380.32
  region net GND: 3722.93,5760.64 ccw(c3709.33,5749.39) 3709.33,5767.04 3753.47,5777.04 3777.61,5767.04 ccw(c3788.71,5694.86) 3737.07,5746.5

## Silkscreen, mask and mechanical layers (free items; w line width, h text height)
Top Silkscreen Layer:
  text "G E+ A- A+" at 3410,3632.97 h45 r90
Top Solder Mask Layer:
  region: 3865,4920.41 3663.52,4920 3663.52,5171.99 3721.53,5230 3935,5230 3935,5055 3865,4985
Bottom Solder Mask Layer:
  region: 3675,5175 3725,5225 3885,5225 3885,5000 3870,4985 3870,4975 3675,4975
Mechanical Layer:
  circle w1: c3294,5838.89 r35.43
  circle w1: c3294,3240.47 r35.43
  circle w1: c4140.46,3240.47 r35.43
